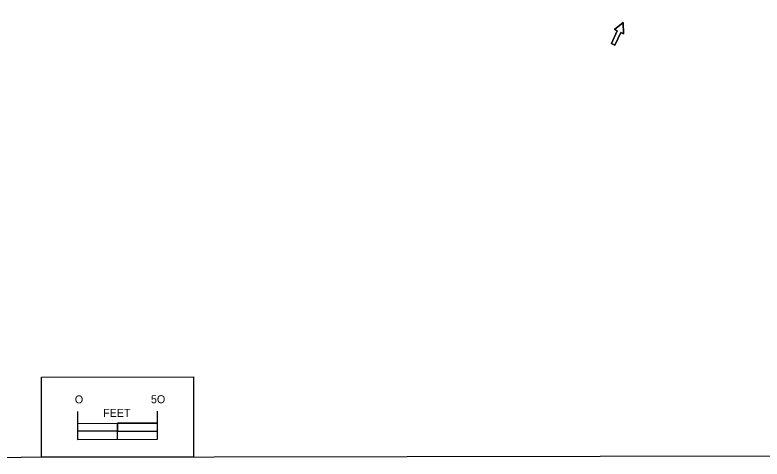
# Model space of a CAD drawing. Extents: x 16513048 to 16518780, y 7009856 to 7010869.
# Drawn here: x 16515768.8 to 16516235.5, y 7009856.4 to 7010134.1 of the extents above; entities that cross this region are included whole.
import ezdxf

# ---------------------------------------------------------------- set-up
doc = ezdxf.new("R2010")
doc.units = 0
for name, color, linetype in [('dsnCellElements', 7, 'Continuous'), ('dsnCellsScaleBlock', 7, 'Continuous'), ('Level 2', 7, 'Continuous'), ('Level 5', 7, 'Continuous'), ('NamedBoundary', 7, 'Continuous')]:
    doc.layers.add(name, color=color, linetype=linetype)

msp = doc.modelspace()

# ---------------------------------------------------------------- linework, layer by layer
at = {"layer": 'dsnCellElements'}
msp.add_lwpolyline([(16515785.32, 7009907.68), (16515880.32, 7009907.85), (16515880.41, 7009857.85), (16515785.41, 7009857.68)], close=True, dxfattribs=at)
msp.add_lwpolyline([(16515785.32, 7009907.68), (16515880.32, 7009907.85), (16515880.41, 7009857.85), (16515785.41, 7009857.68)], close=True, dxfattribs=at)
at = {"layer": 'dsnCellsScaleBlock'}
msp.add_line((16515832.89, 7009868.76), (16515832.88, 7009878.76), dxfattribs=at)
msp.add_line((16515832.89, 7009868.76), (16515832.88, 7009878.76), dxfattribs=at)
for points in [[(16515785.41, 7009857.68), (16515785.32, 7009907.68), (16515880.32, 7009907.85), (16515880.41, 7009857.85)], [(16515832.88, 7009873.8), (16515857.88, 7009873.84), (16515857.88, 7009878.81), (16515832.88, 7009878.76)], [(16515807.89, 7009868.72), (16515832.89, 7009868.76), (16515832.88, 7009873.8), (16515807.88, 7009873.75)]]:
    msp.add_lwpolyline(points, close=True, dxfattribs=at)
for points in [[(16515807.86, 7009886.22), (16515807.89, 7009868.72), (16515857.89, 7009868.81), (16515857.86, 7009886.31)], [(16515807.88, 7009878.72), (16515857.88, 7009878.81)]]:
    msp.add_lwpolyline(points, dxfattribs=at)
at = {"layer": 'Level 2'}
msp.add_lwpolyline([(16516143.6, 7010115.2), (16516141.33, 7010116.25), (16516145.01, 7010124.19), (16516143.31, 7010124.98), (16516148.78, 7010129.33), (16516148.98, 7010122.35), (16516147.28, 7010123.14)], close=True, dxfattribs=at)
at = {"layer": 'Level 5'}
msp.add_lwpolyline([(16516147.28, 7010123.14), (16516148.98, 7010122.35), (16516148.78, 7010129.33), (16516143.31, 7010124.98), (16516145.01, 7010124.19), (16516141.33, 7010116.25), (16516143.6, 7010115.2), (16516147.28, 7010123.14)], dxfattribs=at)
at = {"layer": 'NamedBoundary'}
msp.add_lwpolyline([(16515047.4, 7010866.4), (16515049.16, 7009856.4), (16516616.66, 7009859.13), (16516614.9, 7010869.13)], close=True, dxfattribs=at)

# ---------------------------------------------------------------- texts
at = {"layer": 'dsnCellsScaleBlock'}
for s, p in [('O', (16515806.22, 7009891.22)), ('5O', (16515853.78, 7009891.3)), ('FEET', (16515823.89, 7009882.75))]:
    msp.add_text(s, height=5, rotation=0.0999, dxfattribs=at).set_placement(p)

doc.saveas('drawing.dxf')
